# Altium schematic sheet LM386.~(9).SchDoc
size A4
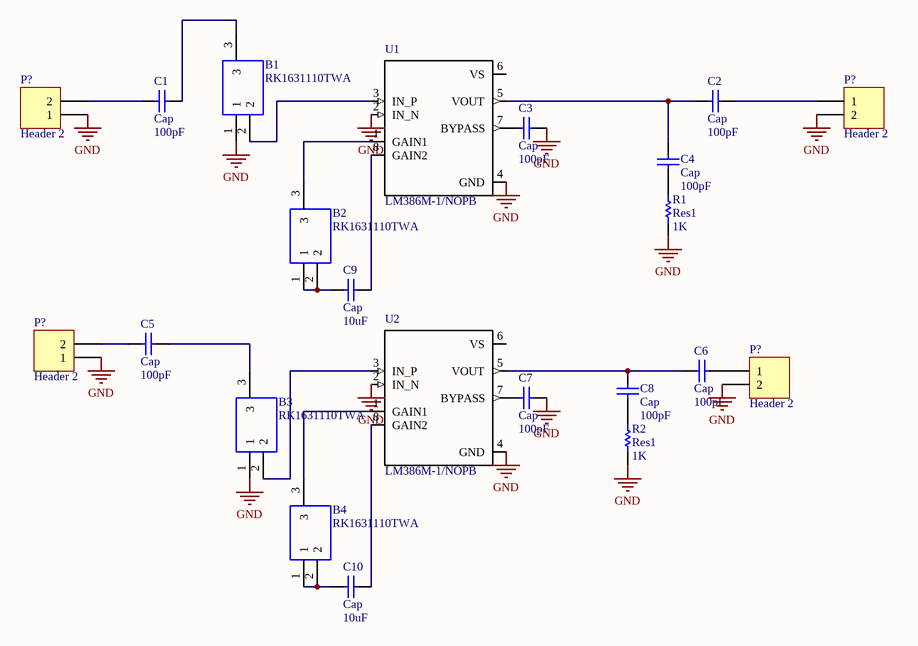
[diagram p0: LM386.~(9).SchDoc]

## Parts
(Parts that share a designator on the sheet are numbered #1, #2 ... from top to bottom, then left to right.)
B1  RK1631110TWA  [RK1631110TWA]
B2  RK1631110TWA  [RK1631110TWA]
B3  RK1631110TWA  [RK1631110TWA]
B4  RK1631110TWA  [RK1631110TWA]
C1  Cap  value 100pF  [RAD-0.3]
C2  Cap  value 100pF  [RAD-0.3]
C3  Cap  value 100pF  [RAD-0.3]
C4  Cap  value 100pF  [RAD-0.3]
C5  Cap  value 100pF  [RAD-0.3]
C6  Cap  value 100pF  [RAD-0.3]
C7  Cap  value 100pF  [RAD-0.3]
C8  Cap  value 100pF  [RAD-0.3]
C9  Cap  value 10uF  [RAD-0.3]
C10  Cap  value 10uF  [RAD-0.3]
P?#1  Header 2  [HDR1X2]
P?#2  Header 2  [HDR1X2]
P?#3  Header 2  [HDR1X2]
P?#4  Header 2  [HDR1X2]
R1  Res1  value 1K  [AXIAL-0.3]
R2  Res1  value 1K  [AXIAL-0.3]
U1  LM386M-1/NOPB  [SOIC127P600X175-8N]
U2  LM386M-1/NOPB  [SOIC127P600X175-8N]

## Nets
GND: B1.1 B3.1 C3.1 C7.2 P?#1.2 P?#2.1 P?#3.2 P?#4.1 R1.1 R2.1 U1.2(IN_N) U1.4(GND) U2.2(IN_N) U2.4(GND)
NetB1_2: B1.2 U1.3(IN_P)
NetB1_3: B1.3 C1.1
NetB2_1: B2.1 B2.2 C9.2
NetB2_3: B2.3 U1.1(GAIN1)
NetB3_2: B3.2 U2.3(IN_P)
NetB3_3: B3.3 C5.1
NetB4_1: B4.1 B4.2 C10.2
NetB4_3: B4.3 U2.1(GAIN1)
NetC1_2: C1.2 P?#2.2
NetC2_1: C2.1 C4.2 U1.5(VOUT)
NetC2_2: C2.2 P?#1.1
NetC3_2: C3.2 U1.7(BYPASS)
NetC4_1: C4.1 R1.2
NetC5_2: C5.2 P?#4.2
NetC6_1: C6.1 C8.2 U2.5(VOUT)
NetC6_2: C6.2 P?#3.1
NetC7_1: C7.1 U2.7(BYPASS)
NetC8_1: C8.1 R2.2
NetC9_1: C9.1 U1.8(GAIN2)
NetC10_1: C10.1 U2.8(GAIN2)

Not connected (* = marked no-connect by the designer): U1 6(VS); U2 6(VS)

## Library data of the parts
B1-B4 = RK1631110TWA: Carbon Film Potentiometer RK163 Series with a 6 mm Dia. Shaft 10k 20% 0.1W; Manufacturer_Name: ALPS
C1-C10 = Cap: Capacitor
P?#1-P?#4 = Header 2: Header, 2-Pin
R1 R2 = Res1: Resistor
U1 U2 = LM386M-1/NOPB: Wide Input Voltage Low Power Audio Amplifier with Internal Gain 8-SOIC 0 to 70; MF: Texas Instruments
